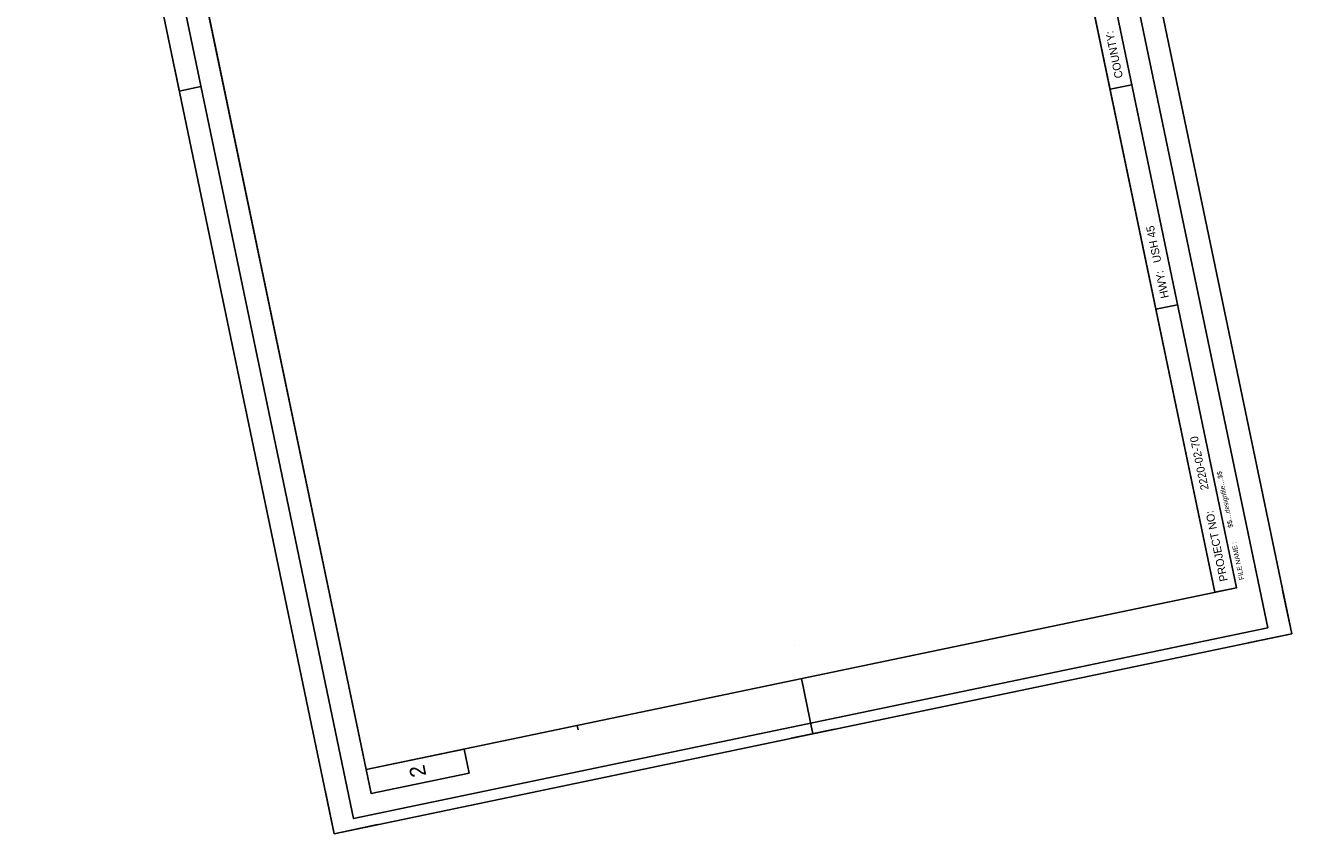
# Model space of a CAD drawing. Extents: x 361335 to 362759, y 126730 to 128619.
# Drawn here: x 361335 to 362759, y 126730 to 127638 of the extents above; entities that cross this region are included whole.
import ezdxf

# ---------------------------------------------------------------- set-up
doc = ezdxf.new("R2010")
doc.units = 0
for name, color, linetype in [('Default', 7, 'Continuous'), ('P_SHTIDX_1 [KAPUR_CADDS_LEVELS]', 7, 'Continuous'), ('P_SHTIDX_2 [KAPUR_CADDS_LEVELS]', 7, 'Continuous'), ('P_SHTIDX_3 [KAPUR_CADDS_LEVELS]', 7, 'Continuous'), ('P_TXT_Plan 3 [KAPUR_CADDS_LEVELS]', 7, 'Continuous')]:
    doc.layers.add(name, color=color, linetype=linetype)

msp = doc.modelspace()

# ---------------------------------------------------------------- linework, layer by layer
at = {"layer": 'Default'}
msp.add_lwpolyline([(361735.9, 128353.1), (361396.8, 128343.8), (361718.5, 126802), (362697.4, 127006.2), (362672.9, 127001.1), (362351.3, 128542.9), (362351.3, 128542.9), (362294.1, 128483.1), (362046.5, 128432.3), (361887.5, 128433.7)], close=True, dxfattribs=at)
msp.add_lwpolyline([(361735.9, 128353.1), (361396.8, 128343.8), (361718.5, 126802), (362697.4, 127006.2), (362672.9, 127001.1), (362351.3, 128542.9), (362351.3, 128542.9), (362294.1, 128483.1), (362046.5, 128432.3), (361887.5, 128433.7)], close=True, dxfattribs=at)
msp.add_lwpolyline([(361735.9, 128353.1), (361396.8, 128343.8), (361718.5, 126802), (362697.4, 127006.2), (362672.9, 127001.1), (362351.3, 128542.9), (362351.3, 128542.9), (362294.1, 128483.1), (362046.5, 128432.3), (361887.5, 128433.7)], close=True, dxfattribs=at)
msp.add_lwpolyline([(361735.9, 128353.1), (361396.8, 128343.8), (361718.5, 126802), (362697.4, 127006.2), (362672.9, 127001.1), (362351.3, 128542.9), (362351.3, 128542.9), (362294.1, 128483.1), (362046.5, 128432.3), (361887.5, 128433.7)], close=True, dxfattribs=at)
msp.add_lwpolyline([(361735.9, 128353.1), (361396.8, 128343.8), (361718.5, 126802), (362697.4, 127006.2), (362672.9, 127001.1), (362351.3, 128542.9), (362351.3, 128542.9), (362294.1, 128483.1), (362046.5, 128432.3), (361887.5, 128433.7)], close=True, dxfattribs=at)
msp.add_lwpolyline([(361735.9, 128353.1), (361396.8, 128343.8), (361718.5, 126802), (362697.4, 127006.2), (362672.9, 127001.1), (362351.3, 128542.9), (362351.3, 128542.9), (362294.1, 128483.1), (362046.5, 128432.3), (361887.5, 128433.7)], close=True, dxfattribs=at)
msp.add_lwpolyline([(361735.9, 128353.1), (361396.8, 128343.8), (361718.5, 126802), (362697.4, 127006.2), (362672.9, 127001.1), (362351.3, 128542.9), (362351.3, 128542.9), (362294.1, 128483.1), (362046.5, 128432.3), (361887.5, 128433.7)], close=True, dxfattribs=at)
msp.add_lwpolyline([(361735.9, 128353.1), (361396.8, 128343.8), (361718.5, 126802), (362697.4, 127006.2), (362672.9, 127001.1), (362351.3, 128542.9), (362351.3, 128542.9), (362294.1, 128483.1), (362046.5, 128432.3), (361887.5, 128433.7)], close=True, dxfattribs=at)
msp.add_lwpolyline([(361735.9, 128353.1), (361396.8, 128343.8), (361718.5, 126802), (362697.4, 127006.2), (362672.9, 127001.1), (362351.3, 128542.9), (362351.3, 128542.9), (362294.1, 128483.1), (362046.5, 128432.3), (361887.5, 128433.7)], close=True, dxfattribs=at)
msp.add_lwpolyline([(361735.9, 128353.1), (361396.8, 128343.8), (361718.5, 126802), (362697.4, 127006.2), (362672.9, 127001.1), (362351.3, 128542.9), (362351.3, 128542.9), (362294.1, 128483.1), (362046.5, 128432.3), (361887.5, 128433.7)], close=True, dxfattribs=at)
at = {"layer": 'P_SHTIDX_1 [KAPUR_CADDS_LEVELS]'}
msp.add_lwpolyline([(361682.5, 126729.8), (361335.3, 128394), (362412.1, 128618.7), (362759.3, 126954.5), (361682.5, 126729.8)], dxfattribs=at)
at = {"layer": 'P_SHTIDX_2 [KAPUR_CADDS_LEVELS]'}
for p, q in [((362697.4, 127006.2), (362375.8, 128548)), ((362672.9, 127001.1), (362351.3, 128542.9)), ((361718.5, 126802), (361396.8, 128343.8)), ((361513.5, 127539.9), (361503.3, 127588.8)), ((361508.4, 127564.4), (361532.8, 127569.5)), ((362579.5, 127571.5), (362555, 127566.4)), ((362631, 127324.3), (362606.6, 127319.2)), ((362697.4, 127006.2), (361718.5, 126802)), ((362759.3, 126954.5), (362749.1, 127003.4)), ((362759.3, 126954.5), (362710.3, 126944.3)), ((362200.3, 126940.8), (362200.3, 126940.8)), ((362220.9, 126842.2), (362208, 126904.1)), ((361955.9, 126851.5), (361956.9, 126846.6)), ((362245.3, 126847.3), (362196.4, 126837.1)), ((361682.5, 126729.8), (361672.3, 126778.8)), ((361731.4, 126740), (361682.5, 126729.8))]:
    msp.add_line(p, q, dxfattribs=at)
msp.add_lwpolyline([(361718.5, 126802), (361724.1, 126775), (361834.2, 126798), (361828.6, 126824.9)], close=True, dxfattribs=at)
at = {"layer": 'P_SHTIDX_3 [KAPUR_CADDS_LEVELS]'}
for points in [[(362759.3, 126954.5), (362412.1, 128618.7), (361335.3, 128394), (361682.5, 126729.8)], [(362732.4, 126961.1), (362394.4, 128581.2), (361366.5, 128366.8), (361704.5, 126746.7)]]:
    msp.add_lwpolyline(points, close=True, dxfattribs=at)
at = {"layer": 'P_TXT_Plan 3 [KAPUR_CADDS_LEVELS]'}
msp.add_lwpolyline([(361682.5, 126729.8), (361335.3, 128394), (362412.1, 128618.7), (362759.3, 126954.5)], close=True, dxfattribs=at)

# ---------------------------------------------------------------- texts
at = {"layer": 'P_SHTIDX_2 [KAPUR_CADDS_LEVELS]'}
for s, height, p in [('COUNTY:', 9, (362569.6, 127579.7)), (' USH 45', 9, (362613.5, 127369.2)), ('HWY:', 9, (362621.2, 127332.5)), (' 2220-02-70', 9, (362666.8, 127113.7)), ('$$....designfile....$$', 5.4, (362693.4, 127074.3)), ('PROJECT NO:', 9, (362687.5, 127014.3)), ('FILE NAME :', 5.4, (362705.7, 127015.6)), ('2', 17.5, (361786.3, 126795.4))]:
    msp.add_text(s, height=height, rotation=101.7841, dxfattribs=at).set_placement(p)

doc.saveas('drawing.dxf')
